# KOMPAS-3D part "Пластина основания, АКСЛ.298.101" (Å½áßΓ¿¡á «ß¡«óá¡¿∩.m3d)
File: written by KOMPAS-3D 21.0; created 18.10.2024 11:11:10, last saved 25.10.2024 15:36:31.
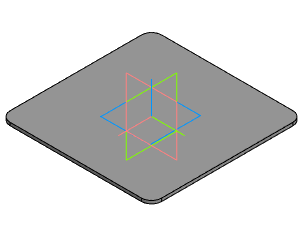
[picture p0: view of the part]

Document properties: Полное имя файла: C:\Users\Алексей Бочаров\YandexDisk\Соединения бруса\Соединения бруса\ОСНОВАНИЕ\Пластина основания.m3d; Автор: Алексей Бочаров

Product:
- Part/product: Пластина основания  | designation АКСЛ.298.101
    Масса: 0.528257
    Форматы листов документа: A4

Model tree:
1. Эскиз:1
2. Элемент выдавливания:1
     Расстояние 2 = 3

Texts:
  АКСЛ.298.101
